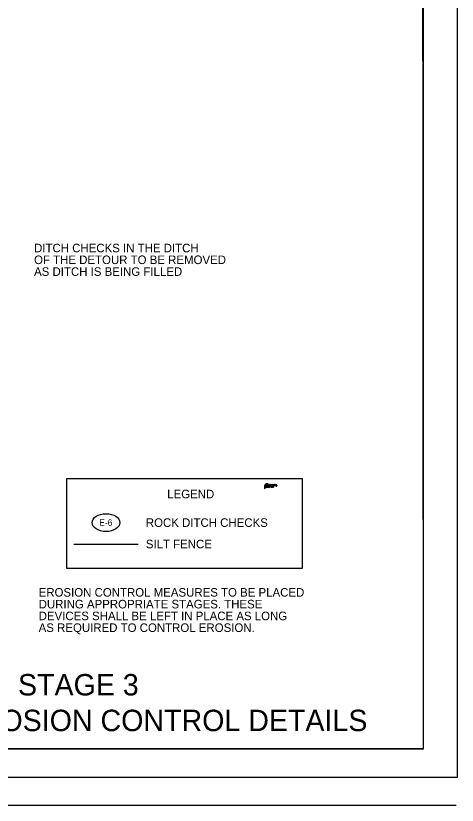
# Model space of a CAD drawing. Extents: x 9525 to 11605, y 9961 to 11067.
# Drawn here: x 11295 to 11605, y 9961 to 10514 of the extents above; entities that cross this region are included whole.
import ezdxf

# ---------------------------------------------------------------- set-up
doc = ezdxf.new("R2010")
doc.units = 0
for name, color, linetype in [('GREEN_TXT', 7, 'Continuous'), ('R_Ditch', 7, 'Continuous'), ('SEAL-INFO', 7, 'Continuous'), ('Stage 1 Ditch Checks', 7, 'Continuous'), ('Stage 2 Construction', 7, 'Continuous'), ('Stage 3 Seeding MAIN', 7, 'Continuous')]:
    doc.layers.add(name, color=color, linetype=linetype)

msp = doc.modelspace()

# ---------------------------------------------------------------- linework, layer by layer
at = {"layer": 'GREEN_TXT'}
for p, q in [((11580.9, 10000), (11580.9, 11027.3)), ((11580.9, 10000), (10000, 10000)), ((9843.9, 9960.6), (11603.9, 9960.6))]:
    msp.add_line(p, q, dxfattribs=at)
at = {"layer": 'R_Ditch'}
for p, q in [((11469.47, 10183.1), (11470.88, 10183.92)), ((11469.48, 10183.63), (11470.68, 10184.33)), ((11469.48, 10182.58), (11471.09, 10183.5)), ((11470.76, 10185.41), (11471.69, 10185.41)), ((11471.71, 10185.39), (11471.81, 10184.8)), ((11473.03, 10184.29), (11473.03, 10184.3)), ((11473.03, 10183.49), (11473.03, 10183.49)), ((11473.04, 10185.3), (11473.04, 10185.3)), ((11473.04, 10184.49), (11473.04, 10184.49)), ((11473.04, 10183.51), (11473.04, 10183.51)), ((11473.06, 10184.51), (11473.05, 10184.51)), ((11473.05, 10183.46), (11473.23, 10183.46)), ((11473.06, 10184.47), (11473.24, 10184.47)), ((11473.06, 10184.25), (11473.06, 10183.53)), ((11473.07, 10185.26), (11473.07, 10184.54)), ((11473.22, 10183.97), (11473.22, 10184.19)), ((11473.22, 10183.53), (11473.22, 10183.85)), ((11473.23, 10184.92), (11473.23, 10185.21)), ((11473.24, 10184.54), (11473.24, 10184.77)), ((11473.24, 10184.21), (11473.64, 10184.21)), ((11473.52, 10183.95), (11473.24, 10183.95)), ((11473.24, 10183.5), (11473.24, 10183.51)), ((11473.25, 10184.8), (11473.5, 10184.87)), ((11473.25, 10184.51), (11473.25, 10184.51)), ((11473.25, 10183.87), (11473.52, 10183.87)), ((11473.25, 10183.49), (11473.25, 10183.49)), ((11473.26, 10185.24), (11473.34, 10185.24)), ((11473.39, 10184.96), (11473.27, 10184.9)), ((11473.27, 10184.49), (11473.27, 10184.49)), ((11473.56, 10183.84), (11473.56, 10183.83)), ((11473.68, 10184.18), (11473.68, 10184.16)), ((11473.8, 10184.49), (11473.8, 10184.49)), ((11473.81, 10184.01), (11473.82, 10184.01)), ((11473.81, 10183.47), (11474.02, 10183.47)), ((11473.82, 10184.47), (11474.03, 10184.47)), ((11473.97, 10184.05), (11473.82, 10184.05)), ((11473.98, 10185.06), (11473.83, 10185.06)), ((11473.83, 10185.02), (11473.83, 10185.01)), ((11473.83, 10183.99), (11473.83, 10183.53)), ((11473.85, 10184.99), (11473.85, 10184.54)), ((11473.99, 10183.54), (11473.99, 10184.03)), ((11474.01, 10184.54), (11474.01, 10185.04)), ((11474.02, 10183.51), (11474.02, 10183.51)), ((11474.03, 10184.51), (11474.03, 10184.52)), ((11474.19, 10183.46), (11474.4, 10183.46)), ((11474.35, 10184.05), (11474.2, 10184.05)), ((11474.2, 10184.01), (11474.2, 10184.01)), ((11474.21, 10183.99), (11474.21, 10183.53)), ((11474.37, 10183.53), (11474.37, 10183.86)), ((11474.4, 10183.51), (11474.4, 10183.51)), ((11474.57, 10184.9), (11474.64, 10184.98)), ((11474.72, 10184.47), (11474.92, 10184.47)), ((11474.72, 10184.01), (11474.72, 10184.01)), ((11474.87, 10185.32), (11474.73, 10185.32)), ((11474.73, 10185.28), (11474.73, 10185.28)), ((11474.73, 10183.99), (11474.73, 10183.53)), ((11474.74, 10185.26), (11474.74, 10184.53)), ((11474.9, 10184.86), (11474.9, 10185.3)), ((11474.9, 10184.69), (11474.97, 10184.75)), ((11474.9, 10184.53), (11474.9, 10184.67)), ((11474.9, 10183.54), (11474.9, 10183.86)), ((11474.92, 10183.51), (11474.92, 10183.51)), ((11475.08, 10184.97), (11474.94, 10184.84)), ((11475.01, 10184.74), (11475.13, 10184.53)), ((11475.08, 10185.04), (11475.09, 10185)), ((11475.31, 10185.07), (11475.1, 10185.07)), ((11475.1, 10183.51), (11475.1, 10183.51)), ((11475.12, 10184.47), (11475.37, 10184.47)), ((11475.12, 10183.86), (11475.12, 10183.54)), ((11475.14, 10184.9), (11475.29, 10185.03)), ((11475.34, 10184.52), (11475.14, 10184.87)), ((11475.28, 10183.54), (11475.28, 10183.87)), ((11475.31, 10185.03), (11475.32, 10185.03)), ((11475.31, 10183.51), (11475.31, 10183.51)), ((11475.33, 10185.04), (11475.33, 10185.05)), ((11475.51, 10184.9), (11475.51, 10184.9)), ((11475.51, 10183.87), (11475.51, 10183.53)), ((11475.52, 10184.82), (11475.87, 10184.82)), ((11475.72, 10184.87), (11475.53, 10184.87)), ((11475.67, 10183.54), (11475.67, 10183.87)), ((11475.7, 10183.51), (11475.69, 10183.51)), ((11475.87, 10184.62), (11475.87, 10184.62)), ((11475.97, 10184.47), (11476.19, 10184.47)), ((11475.98, 10185.02), (11475.98, 10185.01)), ((11476.14, 10185.06), (11475.99, 10185.06)), ((11476, 10184.99), (11476, 10184.54)), ((11476.16, 10184.54), (11476.16, 10184.87)), ((11476.19, 10184.51), (11476.18, 10184.52)), ((11476.44, 10184.47), (11476.65, 10184.47)), ((11476.45, 10185.02), (11476.45, 10185.01)), ((11476.6, 10185.06), (11476.46, 10185.06)), ((11476.47, 10184.99), (11476.47, 10184.54)), ((11476.63, 10184.54), (11476.63, 10185.03)), ((11476.65, 10184.51), (11476.65, 10184.52)), ((11476.76, 10184.47), (11476.97, 10184.47)), ((11476.77, 10185.02), (11476.77, 10185.01)), ((11476.92, 10185.06), (11476.78, 10185.06)), ((11476.79, 10184.99), (11476.79, 10184.54)), ((11476.95, 10184.54), (11476.95, 10184.87)), ((11476.97, 10184.51), (11476.97, 10184.52)), ((11477.15, 10184.47), (11477.36, 10184.47)), ((11477.17, 10184.87), (11477.17, 10184.54)), ((11477.33, 10184.54), (11477.33, 10184.87)), ((11477.36, 10184.51), (11477.36, 10184.52)), ((11478.03, 10185.06), (11477.8, 10185.06)), ((11477.86, 10184.94), (11477.86, 10184.65)), ((11477.88, 10184.46), (11477.88, 10184.46)), ((11478, 10184.63), (11478, 10184.98)), ((11478.01, 10185), (11478.05, 10185.02)), ((11335.77, 10143.59), (11380.77, 10143.59))]:
    msp.add_line(p, q, dxfattribs=at)
msp.add_lwpolyline([(11330.89, 10189.39), (11495.89, 10189.39), (11495.89, 10126.39), (11330.89, 10126.39)], close=True, dxfattribs=at)
for points in [[(11472.14, 10185.07), (11472.02, 10185.76), (11472, 10185.78), (11470.43, 10185.78), (11470.4, 10185.76), (11470.28, 10185.05), (11469.44, 10184.57), (11469.43, 10184.54), (11469.43, 10184.17), (11469.47, 10184.15)], [(11470.51, 10184.66), (11469.45, 10184.04), (11469.44, 10184.02), (11469.44, 10183.65), (11469.48, 10183.63)], [(11470.71, 10184.26), (11469.45, 10183.52), (11469.44, 10183.5), (11469.44, 10183.12), (11469.47, 10183.1)], [(11470.91, 10183.86), (11469.45, 10182.99), (11469.44, 10182.97), (11469.44, 10182.6), (11469.48, 10182.58)], [(11469.47, 10184.15), (11470.61, 10184.78), (11470.62, 10184.8), (11470.73, 10185.39)], [(11472.53, 10184.59), (11472.55, 10184.61), (11472.55, 10184.93), (11472.53, 10184.96)], [(11472.53, 10184.14), (11472.55, 10184.17), (11472.55, 10184.49), (11472.53, 10184.51)], [(11472.53, 10183.69), (11472.55, 10183.71), (11472.55, 10184.04), (11472.53, 10184.06)], [(11472.53, 10183.23), (11472.55, 10183.25), (11472.55, 10183.59), (11472.53, 10183.62)], [(11473.68, 10184.32), (11473.05, 10184.32), (11473.05, 10184.32)], [(11473.43, 10185.33), (11473.06, 10185.33), (11473.06, 10185.32)], [(11473.57, 10184.01), (11473.58, 10184.01), (11473.57, 10184.01), (11473.56, 10184), (11473.56, 10183.98)], [(11473.57, 10183.82), (11473.58, 10183.82), (11473.57, 10183.82)], [(11473.58, 10183.83), (11473.59, 10183.83), (11473.59, 10184), (11473.58, 10184)], [(11473.7, 10184.16), (11473.71, 10184.16), (11473.71, 10184.3)], [(11473.79, 10183.49), (11473.79, 10183.49), (11473.79, 10183.49)], [(11473.8, 10184.03), (11473.8, 10184.03), (11473.8, 10184.03)], [(11473.81, 10185.04), (11473.81, 10185.04), (11473.81, 10185.04)], [(11473.81, 10183.51), (11473.81, 10183.51), (11473.81, 10183.51)], [(11473.82, 10184.52), (11473.82, 10184.52), (11473.82, 10184.51)], [(11474.04, 10183.49), (11474.04, 10183.49), (11474.04, 10183.49)], [(11474.05, 10184.49), (11474.05, 10184.49), (11474.05, 10184.49)], [(11474.17, 10183.49), (11474.17, 10183.49), (11474.17, 10183.49)], [(11474.18, 10184.03), (11474.18, 10184.03), (11474.18, 10184.03)], [(11474.19, 10183.51), (11474.19, 10183.51), (11474.19, 10183.51)], [(11474.42, 10183.49), (11474.42, 10183.49), (11474.42, 10183.49)], [(11474.55, 10183.98), (11474.59, 10183.95), (11474.6, 10183.96), (11474.6, 10184.08), (11474.59, 10184.1), (11474.54, 10184.1)], [(11474.58, 10184.48), (11474.62, 10184.47), (11474.63, 10184.48), (11474.63, 10184.61)], [(11474.69, 10183.49), (11474.71, 10183.47), (11474.92, 10183.47), (11474.94, 10183.49)], [(11474.89, 10184.04), (11474.87, 10184.05), (11474.72, 10184.05), (11474.7, 10184.03)], [(11474.71, 10183.51), (11474.71, 10183.51), (11474.71, 10183.51)], [(11474.72, 10184.52), (11474.72, 10184.52), (11474.72, 10184.51)], [(11474.92, 10184.51), (11474.92, 10184.52), (11474.92, 10184.52)], [(11475.07, 10183.49), (11475.1, 10183.47), (11475.31, 10183.47), (11475.33, 10183.49)], [(11475.12, 10184.52), (11475.12, 10184.52), (11475.12, 10184.51)], [(11475.37, 10184.51), (11475.37, 10184.52), (11475.36, 10184.52)], [(11475.46, 10183.49), (11475.48, 10183.47), (11475.7, 10183.47), (11475.72, 10183.49)], [(11475.49, 10183.51), (11475.49, 10183.51), (11475.48, 10183.51)], [(11475.84, 10184.48), (11475.88, 10184.47), (11475.89, 10184.48), (11475.89, 10184.61)], [(11475.95, 10184.49), (11475.95, 10184.49), (11475.95, 10184.49)], [(11475.97, 10185.04), (11475.97, 10185.03), (11475.97, 10185.04)], [(11475.98, 10184.52), (11475.98, 10184.52), (11475.97, 10184.51)], [(11476.21, 10184.49), (11476.21, 10184.49), (11476.21, 10184.49)], [(11476.34, 10184.99), (11476.38, 10184.95), (11476.39, 10184.97), (11476.39, 10185.09), (11476.38, 10185.1), (11476.32, 10185.1)], [(11476.42, 10184.49), (11476.42, 10184.49), (11476.42, 10184.49)], [(11476.44, 10185.04), (11476.44, 10185.03), (11476.44, 10185.04)], [(11476.45, 10184.52), (11476.44, 10184.52), (11476.44, 10184.51)], [(11476.68, 10184.49), (11476.68, 10184.49), (11476.68, 10184.49)], [(11476.74, 10184.49), (11476.74, 10184.49), (11476.74, 10184.49)], [(11476.75, 10185.04), (11476.75, 10185.03), (11476.75, 10185.04)], [(11476.77, 10184.52), (11476.76, 10184.52), (11476.76, 10184.51)], [(11476.99, 10184.49), (11476.99, 10184.49), (11476.99, 10184.49)], [(11477.13, 10184.49), (11477.13, 10184.49), (11477.13, 10184.49)], [(11477.15, 10184.52), (11477.15, 10184.52), (11477.15, 10184.51)], [(11477.38, 10184.49), (11477.38, 10184.49), (11477.38, 10184.49)], [(11477.56, 10184.31), (11477.56, 10184.36), (11477.55, 10184.38), (11477.51, 10184.4), (11477.41, 10184.32)]]:
    msp.add_lwpolyline(points, dxfattribs=at)
for centre, radius, start, end in [((11471.23, 10183.21), 1.62, 63.44, 116.2443), ((11471.23, 10183.21), 1.24, 63.4399, 116.2445), ((11471.23, 10183.21), 1.16, 63.4396, 116.2455), ((11470.76, 10185.39), 0.0257, 90, 169.3947), ((11471.23, 10183.21), 0.79, 63.4406, 116.2427), ((11471.23, 10183.21), 0.717, 63.443, 116.2359), ((11471.23, 10183.21), 0.326, 63.4385, 116.2484), ((11472.55, 10185.86), 2.63, 243.4196, 269.4358), ((11472.55, 10185.86), 2.24, 243.4196, 269.3512), ((11472.55, 10185.86), 2.17, 243.4196, 269.3138), ((11471.69, 10185.39), 0.0257, 9.4561, 90), ((11472.55, 10185.86), 1.79, 243.4196, 269.1919), ((11472.55, 10185.86), 1.72, 243.4196, 269.1297), ((11471.23, 10183.21), 1.69, 63.4196, 69.8726), ((11472.55, 10185.86), 1.34, 243.4196, 268.9264), ((11472.55, 10185.86), 1.27, 243.4196, 268.8202), ((11472.17, 10185.07), 0.0257, 189.9771, 243.8715), ((11472.55, 10185.86), 0.9, 243.8715, 268.4109), ((11473.05, 10184.3), 0.0212, 82.6236, 189.0072), ((11473.05, 10184.3), 0.0212, 181.5218, 256.2604), ((11473.05, 10183.48), 0.021, 103.7396, 178.4782), ((11473.05, 10183.48), 0.021, 170.9928, 274.1452), ((11473.06, 10185.3), 0.0212, 82.6236, 189.0072), ((11473.06, 10185.3), 0.0212, 181.5218, 256.2604), ((11473.06, 10184.49), 0.021, 103.7396, 178.4782), ((11473.06, 10184.49), 0.021, 170.9928, 274.1452), ((11473.03, 10184.25), 0.0259, 358.7571, 66.0872), ((11473.03, 10183.53), 0.0259, 293.9128, 6.4972), ((11473.04, 10185.26), 0.0259, 358.7571, 66.0872), ((11473.04, 10184.54), 0.0259, 293.9128, 6.4972), ((11473.24, 10184.19), 0.0234, 90, 180), ((11473.24, 10183.97), 0.0234, 180, 270), ((11473.25, 10183.85), 0.0234, 90, 180), ((11473.25, 10183.53), 0.0259, 174.5041, 246.0872), ((11473.26, 10185.21), 0.0234, 90, 180), ((11473.26, 10184.92), 0.0234, 180, 295.644), ((11473.23, 10183.48), 0.021, 260.4108, 9.0072), ((11473.26, 10184.77), 0.0234, 115.5876, 180), ((11473.26, 10184.54), 0.0259, 174.5041, 246.0872), ((11473.25, 10184.49), 0.021, 260.4108, 9.0071), ((11473.23, 10183.48), 0.021, 1.5218, 76.2604), ((11473.25, 10184.49), 0.021, 1.5218, 76.2604), ((11473.37, 10185.07), 0.163, 26.6835, 99.2796), ((11473.1, 10185.44), 0.563, 300.9494, 314.2537), ((11473.47, 10184.87), 0.455, 79.5817, 94.0737), ((11473.44, 10185.11), 0.0889, 308.8414, 26.6835), ((11473.25, 10185.45), 0.631, 293.1872, 299.0408), ((11473.52, 10183.98), 0.0351, 270, 0), ((11473.52, 10183.84), 0.0351, 0, 90), ((11473.51, 10185.12), 0.205, 346.8336, 79.1626), ((11473.47, 10185.13), 0.242, 290.3558, 346.8336), ((11473.57, 10183.83), 0.0117, 180, 270), ((11473.57, 10184), 0.0117, 0, 90), ((11473.57, 10183.83), 0.0117, 270, 0), ((11473.64, 10184.18), 0.0351, 360, 90), ((11473.68, 10184.3), 0.0234, 360, 90), ((11473.69, 10184.16), 0.0117, 180, 270), ((11473.69, 10184.16), 0.0117, 270, 0), ((11473.81, 10183.49), 0.0211, 90, 180), ((11473.81, 10183.49), 0.0211, 180, 270), ((11473.82, 10184.49), 0.0211, 90, 179.9884), ((11473.82, 10184.49), 0.0211, 180, 270), ((11473.82, 10184.03), 0.0211, 90, 180), ((11473.82, 10184.03), 0.0211, 180, 250.953), ((11473.83, 10185.04), 0.0211, 90, 180), ((11473.83, 10185.04), 0.0211, 180, 250.953), ((11473.81, 10183.53), 0.0211, 270, 360), ((11473.82, 10184.54), 0.0211, 270, 360), ((11473.81, 10183.99), 0.0234, 0, 70.953), ((11473.82, 10184.99), 0.0234, 0, 70.953), ((11473.93, 10185.23), 0.0853, 0, 180), ((11473.93, 10185.23), 0.0853, 180, 0), ((11473.97, 10184.03), 0.0234, 0, 90), ((11473.98, 10185.04), 0.0234, 0, 90), ((11474.02, 10183.54), 0.0234, 180, 270), ((11474.03, 10184.54), 0.0234, 180, 270), ((11474.02, 10183.49), 0.0211, 360, 90), ((11474.02, 10183.49), 0.0211, 270, 0), ((11474.03, 10184.49), 0.0211, 0, 90), ((11474.03, 10184.49), 0.0211, 270, 0), ((11474.43, 10184.8), 0.335, 159.4493, 258.0401), ((11474.35, 10184.86), 0.236, 89.5501, 165.3049), ((11474.19, 10183.49), 0.0211, 90, 180), ((11474.19, 10183.49), 0.0211, 180, 270), ((11474.2, 10184.03), 0.0211, 90, 180), ((11474.2, 10184.03), 0.0211, 180, 250.953), ((11474.19, 10183.53), 0.0211, 270, 0), ((11474.19, 10183.99), 0.0234, 360, 70.953), ((11474.6, 10184.8), 0.336, 157.5816, 204.7596), ((11474.43, 10184.84), 0.166, 85.3224, 146.7414), ((11474.49, 10184.8), 0.242, 216.7971, 248.1851), ((11474.34, 10184.62), 0.476, 51.4978, 89.5501), ((11474.35, 10184.03), 0.0234, 31.1414, 90), ((11474.45, 10184.87), 0.404, 257.1029, 287.6234), ((11474.38, 10184.05), 0.0117, 211.1414, 301.6677), ((11474.52, 10183.85), 0.142, 82.1433, 175.2273), ((11474.4, 10183.53), 0.0234, 180, 270), ((11474.62, 10183.66), 0.44, 100.4967, 121.6677), ((11474.47, 10184.79), 0.222, 251.3493, 311.1706), ((11474.4, 10183.49), 0.0211, 360, 90), ((11474.4, 10183.49), 0.0211, 270, 0), ((11474.42, 10184.8), 0.199, 60.5413, 85.3224), ((11474.49, 10184.92), 0.0688, 353.0776, 57.5568), ((11474.53, 10183.97), 0.0234, 33.0334, 82.1433), ((11474.57, 10184.91), 0.0117, 173.0776, 318.3482), ((11474.58, 10184.47), 0.0117, 72.7237, 107.6234), ((11474.62, 10184.61), 0.0117, 0, 131.1706), ((11474.63, 10184.98), 0.0117, 318.3482, 51.4978), ((11474.71, 10183.49), 0.0211, 90, 173.9744), ((11474.72, 10184.49), 0.0211, 90, 180), ((11474.72, 10184.49), 0.0211, 180, 270), ((11474.72, 10184.03), 0.0211, 185.1813, 250.953), ((11474.73, 10185.3), 0.0211, 90, 180), ((11474.73, 10185.3), 0.0211, 180, 250.953), ((11474.71, 10183.53), 0.0211, 270, 0), ((11474.72, 10184.53), 0.0187, 270, 360), ((11474.71, 10183.99), 0.0234, 360, 70.953), ((11474.72, 10185.26), 0.0234, 360, 70.953), ((11474.87, 10185.3), 0.0234, 360, 90), ((11474.9, 10184.05), 0.0117, 211.1414, 301.6677), ((11475.01, 10183.87), 0.114, 354.6239, 185.3761), ((11474.92, 10184.86), 0.0234, 180, 311.0699), ((11474.92, 10184.67), 0.0234, 131.0699, 180), ((11474.92, 10184.53), 0.0187, 180, 270), ((11474.92, 10183.54), 0.0234, 180, 270), ((11475.06, 10183.88), 0.221, 38.0335, 134.0608), ((11474.92, 10184.49), 0.0211, 0, 90), ((11474.92, 10184.49), 0.0211, 270, 0), ((11474.92, 10183.49), 0.0211, 6.0256, 90), ((11474.99, 10184.73), 0.0234, 31.2702, 131.0699), ((11475.1, 10183.49), 0.0211, 90, 173.9744), ((11475.1, 10185.05), 0.0234, 90, 199.4367), ((11475.07, 10184.99), 0.0234, 311.0699, 19.4367), ((11475.12, 10184.49), 0.0211, 90, 180), ((11475.12, 10184.49), 0.0211, 180, 270), ((11475.1, 10183.54), 0.0234, 270, 0), ((11475.12, 10184.53), 0.0117, 270, 31.2702), ((11475.16, 10184.88), 0.0234, 131.0699, 211.2702), ((11475.25, 10184.03), 0.0234, 218.0335, 322.8576), ((11475.45, 10183.88), 0.221, 355.8732, 142.8576), ((11475.4, 10183.88), 0.114, 354.6239, 185.3761), ((11475.31, 10183.54), 0.0234, 180, 270), ((11475.31, 10185.01), 0.0234, 90, 131.0699), ((11475.31, 10185.05), 0.0234, 0, 90), ((11475.31, 10183.49), 0.0211, 6.0256, 90), ((11475.32, 10185.04), 0.0117, 270, 0), ((11475.66, 10184.8), 0.335, 159.4493, 258.0401), ((11475.36, 10184.53), 0.0187, 211.2702, 270), ((11475.57, 10184.86), 0.236, 89.5501, 165.3049), ((11475.37, 10184.49), 0.0211, 0, 90), ((11475.37, 10184.49), 0.0211, 270, 0), ((11475.48, 10183.49), 0.0211, 90, 173.9744), ((11475.52, 10184.79), 0.0234, 90, 181.0387), ((11475.83, 10184.8), 0.336, 181.0387, 204.7596), ((11475.49, 10183.53), 0.0211, 270, 0), ((11475.83, 10184.8), 0.336, 157.5816, 162.6114), ((11475.53, 10184.89), 0.0234, 162.6114, 270), ((11475.63, 10184.89), 0.117, 0.3238, 162.4345), ((11475.72, 10184.8), 0.242, 216.7971, 248.1851), ((11475.57, 10184.62), 0.476, 70.5239, 89.5501), ((11475.69, 10184.99), 0.52, 258.6424, 285.5129), ((11475.71, 10184.85), 0.279, 253.3482, 306.5566), ((11475.69, 10183.54), 0.0234, 180, 270), ((11475.7, 10183.49), 0.0211, 6.0256, 90), ((11475.72, 10184.89), 0.0234, 270, 0.3238), ((11475.67, 10184.85), 0.226, 357.7955, 73.16), ((11475.84, 10184.47), 0.0117, 72.7237, 107.6234), ((11475.87, 10184.84), 0.0234, 270, 11.363), ((11475.88, 10184.61), 0.0117, 360, 131.1706), ((11475.97, 10184.49), 0.0211, 90, 180), ((11475.97, 10184.49), 0.0211, 180, 270), ((11475.99, 10185.04), 0.0211, 90, 180), ((11475.99, 10185.04), 0.0211, 180, 250.953), ((11475.98, 10184.99), 0.0234, 0, 70.953), ((11475.98, 10184.54), 0.0211, 270, 0), ((11476.14, 10185.03), 0.0234, 31.1414, 90), ((11476.17, 10185.05), 0.0117, 211.1414, 301.6677), ((11476.3, 10184.86), 0.142, 82.1433, 175.2273), ((11476.18, 10184.54), 0.0234, 180, 270), ((11476.4, 10184.67), 0.44, 100.4967, 121.6677), ((11476.19, 10184.49), 0.0211, 0, 90), ((11476.19, 10184.49), 0.0211, 270, 360), ((11476.32, 10184.97), 0.0234, 33.0334, 82.1433), ((11476.44, 10184.49), 0.0211, 90, 180), ((11476.44, 10184.49), 0.0211, 180, 270), ((11476.46, 10185.04), 0.0211, 90, 180), ((11476.46, 10185.04), 0.0211, 180, 250.953), ((11476.44, 10184.99), 0.0234, 0, 70.953), ((11476.45, 10184.54), 0.0211, 270, 0), ((11476.54, 10185.23), 0.0853, 0, 180), ((11476.54, 10185.23), 0.0853, 180, 0), ((11476.6, 10185.03), 0.0234, 0, 90), ((11476.65, 10184.54), 0.0234, 180, 270), ((11476.65, 10184.49), 0.0211, 0, 90), ((11476.65, 10184.49), 0.0211, 270, 0), ((11476.76, 10184.49), 0.0211, 90, 180), ((11476.76, 10184.49), 0.0211, 180, 270), ((11476.78, 10185.04), 0.0211, 90, 180), ((11476.78, 10185.04), 0.0211, 180, 250.953), ((11476.76, 10184.99), 0.0234, 0, 70.953), ((11476.77, 10184.54), 0.0211, 270, 0), ((11476.92, 10185.03), 0.0234, 31.1414, 90), ((11476.95, 10185.05), 0.0117, 211.1414, 301.6677), ((11477.06, 10184.88), 0.114, 354.6239, 185.3761), ((11476.97, 10184.54), 0.0234, 180, 270), ((11477.11, 10184.88), 0.221, 355.8732, 134.0608), ((11476.97, 10184.49), 0.0211, 0, 90), ((11476.97, 10184.49), 0.0211, 270, 0), ((11477.15, 10184.49), 0.0211, 90, 180), ((11477.15, 10184.49), 0.0211, 180, 270), ((11477.15, 10184.54), 0.0211, 270, 0), ((11477.36, 10184.54), 0.0234, 180, 270), ((11477.36, 10184.49), 0.0211, 0, 90), ((11477.36, 10184.49), 0.0211, 270, 0), ((11477.43, 10184.3), 0.0234, 131.168, 231.4342), ((11477.73, 10184.69), 0.516, 231.4342, 293.5615), ((11477.75, 10184.73), 0.334, 82.2082, 193.6815), ((11477.65, 10184.71), 0.236, 194.6951, 270.4499), ((11477.59, 10184.31), 0.0234, 180, 236.707), ((11477.69, 10184.47), 0.211, 236.707, 290.0983), ((11477.81, 10184.74), 0.225, 83.4753, 215.9717), ((11477.73, 10184.7), 0.138, 223.5865, 338.2119), ((11477.55, 10185.07), 0.606, 280.0346, 297.3499), ((11477.73, 10184.43), 0.158, 282.8124, 14.1312), ((11477.84, 10184.51), 0.0234, 13.323, 128.4784), ((11477.84, 10184.94), 0.0234, 0, 83.4753), ((11478.39, 10184.64), 0.539, 193.323, 199.0669), ((11478.39, 10184.64), 0.539, 199.0669, 199.752), ((11477.83, 10184.39), 0.213, 302.2961, 7.2223), ((11478.02, 10184.98), 0.0234, 135.4319, 180), ((11478.42, 10184.6), 0.419, 175.3173, 204.9345), ((11478.03, 10185.03), 0.0234, 315.4319, 90)]:
    msp.add_arc(centre, radius, start, end, dxfattribs=at)
msp.add_ellipse((11358.27, 10158.59), major_axis=(9.78, 0), ratio=0.638788, dxfattribs=at)
at = {"layer": 'SEAL-INFO'}
msp.add_lwpolyline([(9937.96, 11046.77), (11604.66, 11046.77), (11604.66, 9980.09), (9937.96, 9980.09)], close=True, dxfattribs=at)
at = {"layer": 'Stage 1 Ditch Checks'}
msp.add_lwpolyline([(10000, 10000), (11580.9, 10000), (11580.3, 10963.3), (11365.4, 10963.3), (11357.31, 10959.87), (11348.49, 10961.4), (11348.26, 10977.9), (11169.6, 10977.9), (11169.6, 11027.3), (10000, 11027.3)], close=True, dxfattribs=at)
msp.add_lwpolyline([(10000, 10000), (11580.9, 10000), (11580.3, 10963.3), (11365.4, 10963.3), (11357.31, 10959.87), (11348.49, 10961.4), (11348.26, 10977.9), (11169.6, 10977.9), (11169.6, 11027.3), (10000, 11027.3)], close=True, dxfattribs=at)

# ---------------------------------------------------------------- texts
at = {"layer": 'GREEN_TXT'}
for s, p in [('STAGE 3', (11296.53, 10037.5)), ('TEMPORARY EROSION CONTROL DETAILS', (11123.73, 10012.5))]:
    msp.add_text(s, height=15, dxfattribs=at).set_placement(p)
at = {"layer": 'R_Ditch'}
for s, height, p in [('LEGEND', 6, (11401.21, 10175.59)), ('E-6', 4.464, (11353.49, 10156.36)), ('ROCK DITCH CHECKS', 6, (11386.21, 10155.59)), ('SILT FENCE', 6, (11386.21, 10140.59))]:
    msp.add_text(s, height=height, dxfattribs=at).set_placement(p)
at = {"layer": 'Stage 2 Construction'}
for s, p in [('EROSION CONTROL MEASURES TO BE PLACED ', (11311.04, 10106.72)), ('DURING APPROPRIATE STAGES. THESE ', (11311.04, 10098.47)), ('DEVICES SHALL BE LEFT IN PLACE AS LONG ', (11311.04, 10090.22)), ('AS REQUIRED TO CONTROL EROSION.', (11311.04, 10081.97))]:
    msp.add_text(s, height=6, dxfattribs=at).set_placement(p)
at = {"layer": 'Stage 3 Seeding MAIN'}
for s, p in [('DITCH CHECKS IN THE DITCH', (11307.82, 10347.95)), ('OF THE DETOUR TO BE REMOVED', (11307.82, 10339.7)), ('AS DITCH IS BEING FILLED', (11307.82, 10331.45))]:
    msp.add_text(s, height=6, dxfattribs=at).set_placement(p)

doc.saveas('drawing.dxf')
